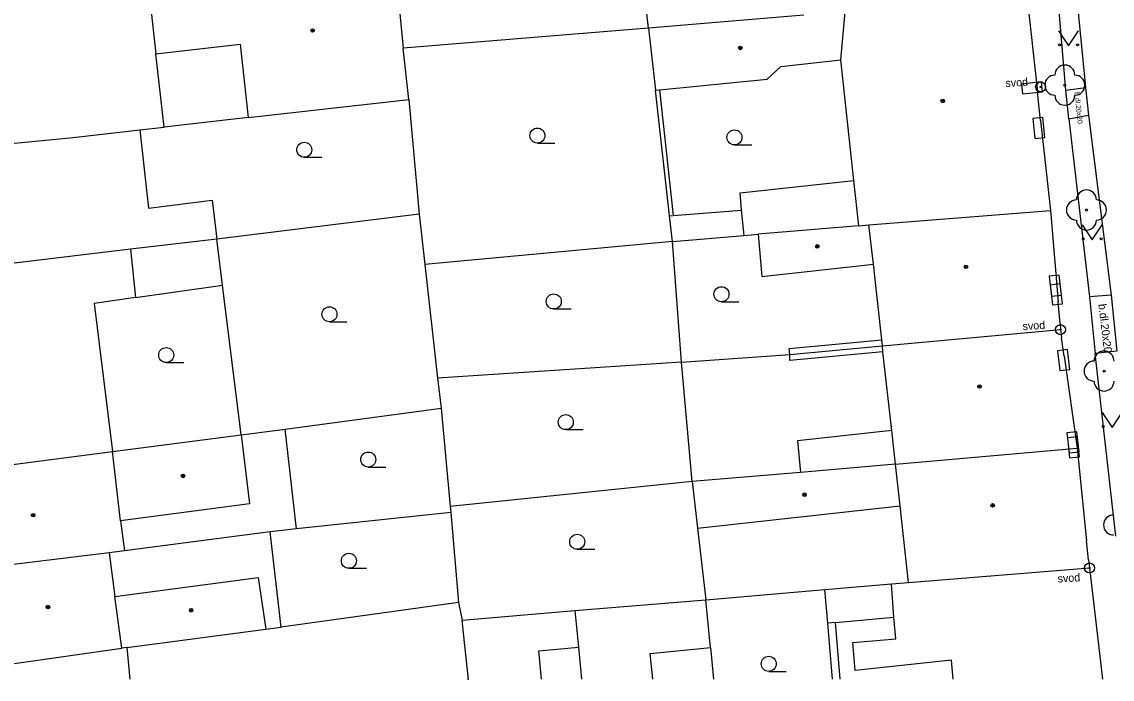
# Model space of a CAD drawing. Extents: x -596229 to -595156, y -1161237 to -1159376.
# Drawn here: x -595832.9 to -595778.4, y -1161235.4 to -1161202.6 of the extents above; entities that cross this region are included whole.
import ezdxf

# ---------------------------------------------------------------- set-up
doc = ezdxf.new("R2010")
doc.units = 0
for name, color, linetype in [('DOP - kresba z DSPS bez souradnic', 7, 'Continuous'), ('DOP - rozhrani ploch obecne', 7, 'Continuous'), ('Level 22', 7, 'Continuous'), ('Level 24', 7, 'Continuous'), ('Level 25', 7, 'Continuous'), ('Level 36', 7, 'Continuous'), ('Level 39', 7, 'Continuous'), ('TM - budovy zdene_ betonove - VP', 7, 'Continuous'), ('TM - chodniky - VP', 7, 'Continuous'), ('TM - komunikace - VP', 7, 'Continuous'), ('TM - plot zdeny_ ohradni zed - VP', 7, 'Continuous'), ('TM - popis povrchu', 7, 'Continuous'), ('TM - poznamka', 7, 'Continuous'), ('TM - rozhrani mezi zpev. plochami mezi sebou - VP', 7, 'Continuous'), ('TM - vstup do budovy - zdene_ betonove', 7, 'Continuous')]:
    doc.layers.add(name, color=color, linetype=linetype)

msp = doc.modelspace()

# ---------------------------------------------------------------- linework, layer by layer
at = {"layer": 'DOP - kresba z DSPS bez souradnic'}
for points in [[(-595801.04, -1161205.96), (-595800.36, -1161212.24)], [(-595797.01, -1161211.11), (-595791.33, -1161210.49)], [(-595796.95, -1161211.98), (-595797.01, -1161211.11)], [(-595800.36, -1161212.24), (-595796.95, -1161211.98)], [(-595796.81, -1161213.24), (-595796.95, -1161211.98)], [(-595800.54, -1161212.26), (-595800.36, -1161212.24)], [(-595827.24, -1161216.34), (-595822.88, -1161215.73)], [(-595794.56, -1161218.89), (-595789.94, -1161218.46)], [(-595794.54, -1161219.19), (-595794.56, -1161218.89)], [(-595789.88, -1161219.05), (-595794.53, -1161219.49)], [(-595794.53, -1161219.49), (-595794.54, -1161219.19)], [(-595789.44, -1161222.99), (-595794.15, -1161223.51)], [(-595794.15, -1161223.51), (-595794, -1161225.08)], [(-595792.25, -1161232.58), (-595792.64, -1161232.62)], [(-595792.25, -1161232.58), (-595789.33, -1161232.32)], [(-595792.018, -1161235.417), (-595792.25, -1161232.58)]]:
    msp.add_lwpolyline(points, dxfattribs=at)
at = {"layer": 'DOP - rozhrani ploch obecne'}
for points in [[(-595801.59, -1161202.89), (-595801.97, -1161199.66)], [(-595801.59, -1161202.89), (-595813.86, -1161203.88)], [(-595800.54, -1161212.26), (-595801.24, -1161205.98)], [(-595813.58, -1161206.44), (-595813.06, -1161212.18)], [(-595813.06, -1161212.18), (-595823.17, -1161213.42)], [(-595813.06, -1161212.18), (-595812.77, -1161214.69)], [(-595800.4, -1161213.54), (-595800.54, -1161212.26)], [(-595822.88, -1161215.73), (-595823.17, -1161213.42)], [(-595800.4, -1161213.54), (-595812.77, -1161214.69)], [(-595800.4, -1161213.54), (-595796.81, -1161213.24)], [(-595799.94, -1161219.57), (-595800.4, -1161213.54)], [(-595796.81, -1161213.24), (-595796.12, -1161213.18)], [(-595812.77, -1161214.69), (-595812.14, -1161220.37)], [(-595821.95, -1161223.2), (-595822.88, -1161215.73)], [(-595794.54, -1161219.19), (-595789.91, -1161218.75)], [(-595799.94, -1161219.57), (-595812.14, -1161220.37)], [(-595799.94, -1161219.57), (-595794.54, -1161219.19)], [(-595799.42, -1161225.54), (-595799.94, -1161219.57)], [(-595812.14, -1161220.37), (-595811.95, -1161221.88)], [(-595819.75, -1161222.92), (-595811.95, -1161221.88)], [(-595811.95, -1161221.88), (-595811.5, -1161226.78)], [(-595821.95, -1161223.2), (-595819.75, -1161222.92)], [(-595819.19, -1161227.9), (-595819.75, -1161222.92)], [(-595799.42, -1161225.54), (-595811.5, -1161226.78)], [(-595811.47, -1161227.08), (-595819.19, -1161227.9)], [(-595811.5, -1161226.78), (-595811.47, -1161227.08)], [(-595811.47, -1161227.08), (-595811.09, -1161231.59)], [(-595820.5, -1161228.05), (-595827.78, -1161229.01)], [(-595819.19, -1161227.9), (-595820.5, -1161228.05)], [(-595819.96, -1161232.81), (-595820.5, -1161228.05)], [(-595799.15, -1161227.87), (-595798.73, -1161231.45)], [(-595798.73, -1161231.45), (-595792.78, -1161230.94)], [(-595792.78, -1161230.94), (-595789.45, -1161230.66)], [(-595792.64, -1161232.62), (-595792.78, -1161230.94)], [(-595811.09, -1161231.59), (-595819.96, -1161232.81)], [(-595811.09, -1161231.59), (-595810.91, -1161232.46)], [(-595805.28, -1161231.99), (-595798.73, -1161231.45)], [(-595798.5, -1161233.84), (-595798.73, -1161231.45)], [(-595810.91, -1161232.46), (-595805.28, -1161231.99)], [(-595805.28, -1161231.99), (-595805.1, -1161233.81)], [(-595810.76, -1161233.9), (-595810.91, -1161232.46)], [(-595792.398, -1161235.417), (-595792.64, -1161232.62)], [(-595820.72, -1161232.91), (-595819.96, -1161232.81)], [(-595810.6, -1161235.41), (-595810.76, -1161233.9)], [(-595810.639, -1161235.417), (-595810.6, -1161235.41)], [(-595810.6, -1161235.41), (-595810.599, -1161235.417)]]:
    msp.add_lwpolyline(points, dxfattribs=at)
at = {"layer": 'Level 22'}
for centre in [(-595780.79, -1161205.73), (-595779.71, -1161211.97), (-595778.83, -1161220.02)]:
    msp.add_circle(centre, 0.05, dxfattribs=at)
for centre, start, end in [((-595780.79, -1161205.23), 0, 180), ((-595781.29, -1161205.73), 90, 270), ((-595780.29, -1161205.73), 270, 90), ((-595780.79, -1161206.23), 180, 0), ((-595779.71, -1161211.47), 0, 180), ((-595780.21, -1161211.97), 90, 270), ((-595779.21, -1161211.97), 270, 90), ((-595779.71, -1161212.47), 180, 0), ((-595778.83, -1161219.52), 0, 180), ((-595779.33, -1161220.02), 90, 270), ((-595778.83, -1161220.52), 180, 0), ((-595778.36, -1161227.71), 90, 270)]:
    msp.add_arc(centre, 0.5, start, end, dxfattribs=at)
at = {"layer": 'Level 24'}
for points in [[(-595781.96, -1161205.568), (-595782.954, -1161205.675), (-595782.9, -1161206.172), (-595781.906, -1161206.065)], [(-595782.392, -1161207.4), (-595782.285, -1161208.394), (-595781.788, -1161208.34), (-595781.895, -1161207.346)], [(-595781.576, -1161215.282), (-595781.46, -1161216.276), (-595780.964, -1161216.218), (-595781.08, -1161215.224)], [(-595781.526, -1161215.722), (-595781.41, -1161216.716), (-595780.914, -1161216.658), (-595781.03, -1161215.664)], [(-595781.154, -1161219.001), (-595781.043, -1161219.995), (-595780.546, -1161219.939), (-595780.657, -1161218.945)], [(-595780.684, -1161223.111), (-595780.573, -1161224.105), (-595780.076, -1161224.049), (-595780.187, -1161223.055)], [(-595780.664, -1161223.361), (-595780.553, -1161224.355), (-595780.056, -1161224.299), (-595780.167, -1161223.305)]]:
    msp.add_lwpolyline(points, close=True, dxfattribs=at)
at = {"layer": 'Level 25'}
for centre, radius in [((-595782, -1161205.82), 0.25), ((-595782, -1161205.82), 0.0303), ((-595781.01, -1161217.95), 0.25), ((-595781.01, -1161217.95), 0.0303), ((-595779.56, -1161229.86), 0.25), ((-595779.56, -1161229.86), 0.0303)]:
    msp.add_circle(centre, radius, dxfattribs=at)
at = {"layer": 'Level 36'}
for p, q in [((-595807.15, -1161208.625), (-595806.275, -1161208.625)), ((-595797.3, -1161208.715), (-595796.425, -1161208.715)), ((-595818.8, -1161209.335), (-595817.925, -1161209.335)), ((-595797.95, -1161216.555), (-595797.075, -1161216.555)), ((-595806.33, -1161216.915), (-595805.455, -1161216.915)), ((-595817.54, -1161217.555), (-595816.665, -1161217.555)), ((-595825.7, -1161219.595), (-595824.825, -1161219.595)), ((-595805.73, -1161222.945), (-595804.855, -1161222.945)), ((-595815.6, -1161224.815), (-595814.725, -1161224.815)), ((-595805.16, -1161228.925), (-595804.285, -1161228.925)), ((-595816.57, -1161229.875), (-595815.695, -1161229.875)), ((-595795.59, -1161235.025), (-595794.715, -1161235.025))]:
    msp.add_line(p, q, dxfattribs=at)
for points in [[(-595781.1, -1161203.01), (-595780.6, -1161203.76), (-595780.1, -1161203.01)], [(-595779.93, -1161212.71), (-595779.43, -1161213.46), (-595778.93, -1161212.71)], [(-595778.93, -1161222.09), (-595778.43, -1161222.84), (-595777.93, -1161222.09)]]:
    msp.add_lwpolyline(points, dxfattribs=at)
for centre, radius in [((-595781.05, -1161203.71), 0.05), ((-595780.151, -1161203.71), 0.05), ((-595807.15, -1161208.25), 0.375), ((-595797.3, -1161208.34), 0.375), ((-595818.8, -1161208.96), 0.375), ((-595779.88, -1161213.41), 0.05), ((-595778.981, -1161213.41), 0.05), ((-595806.33, -1161216.54), 0.375), ((-595797.95, -1161216.18), 0.375), ((-595817.54, -1161217.18), 0.375), ((-595825.7, -1161219.22), 0.375), ((-595805.73, -1161222.57), 0.375), ((-595778.88, -1161222.79), 0.05), ((-595815.6, -1161224.44), 0.375), ((-595805.16, -1161228.55), 0.375), ((-595816.57, -1161229.5), 0.375), ((-595795.59, -1161234.65), 0.375)]:
    msp.add_circle(centre, radius, dxfattribs=at)
at = {"layer": 'Level 39'}
for centre, radius in [((-595818.38, -1161203), 0.09), ((-595818.38, -1161203), 0.0398), ((-595797.01, -1161203.87), 0.09), ((-595797.01, -1161203.87), 0.0398), ((-595786.89, -1161206.52), 0.09), ((-595786.89, -1161206.52), 0.0398), ((-595793.16, -1161213.79), 0.09), ((-595793.16, -1161213.79), 0.0398), ((-595785.73, -1161214.81), 0.09), ((-595785.73, -1161214.81), 0.0398), ((-595785.06, -1161220.79), 0.09), ((-595785.06, -1161220.79), 0.0398), ((-595824.86, -1161225.26), 0.09), ((-595824.86, -1161225.26), 0.0398), ((-595793.8, -1161226.2), 0.09), ((-595793.8, -1161226.2), 0.0398), ((-595784.4, -1161226.73), 0.09), ((-595784.4, -1161226.73), 0.0398), ((-595832.35, -1161227.22), 0.09), ((-595832.35, -1161227.22), 0.0398), ((-595831.61, -1161231.81), 0.09), ((-595831.61, -1161231.81), 0.0398), ((-595824.45, -1161231.97), 0.09), ((-595824.45, -1161231.97), 0.0398)]:
    msp.add_circle(centre, radius, dxfattribs=at)
at = {"layer": 'TM - budovy zdene_ betonove - VP'}
for points in [[(-595814.33, -1161199.05), (-595813.86, -1161203.88)], [(-595826.61, -1161200.53), (-595826.21, -1161204.17)], [(-595782.67, -1161201.38), (-595782.15, -1161206.07)], [(-595791.98, -1161204.47), (-595791.77, -1161202.07)], [(-595793.84, -1161202.24), (-595801.59, -1161202.89)], [(-595801.59, -1161202.89), (-595801.24, -1161205.98)], [(-595826.21, -1161204.17), (-595822.01, -1161203.69)], [(-595822.01, -1161203.69), (-595821.6, -1161207.35)], [(-595825.8, -1161207.83), (-595826.21, -1161204.17)], [(-595813.58, -1161206.44), (-595813.86, -1161203.88)], [(-595795.66, -1161205.43), (-595794.98, -1161204.8)], [(-595794.98, -1161204.8), (-595791.98, -1161204.47)], [(-595791.33, -1161210.49), (-595791.98, -1161204.47)], [(-595801.04, -1161205.96), (-595795.66, -1161205.43)], [(-595801.24, -1161205.98), (-595801.04, -1161205.96)], [(-595821.6, -1161207.35), (-595813.58, -1161206.44)], [(-595782, -1161207.49), (-595781.5, -1161211.99)], [(-595830.35, -1161208.34), (-595827.01, -1161207.97)], [(-595827.01, -1161207.97), (-595825.8, -1161207.83)], [(-595827.01, -1161207.97), (-595826.58, -1161211.87)], [(-595839.85, -1161209.26), (-595830.35, -1161208.34)], [(-595791.08, -1161212.76), (-595791.33, -1161210.49)], [(-595826.58, -1161211.87), (-595823.41, -1161211.48)], [(-595823.41, -1161211.48), (-595823.17, -1161213.42)], [(-595790.58, -1161212.71), (-595781.5, -1161211.99)], [(-595781.5, -1161211.99), (-595781.12, -1161216.56)], [(-595791.08, -1161212.76), (-595796.12, -1161213.18)], [(-595791.08, -1161212.76), (-595790.58, -1161212.71)], [(-595790.36, -1161214.68), (-595790.58, -1161212.71)], [(-595823.17, -1161213.42), (-595827.48, -1161213.93)], [(-595796.12, -1161213.18), (-595795.93, -1161215.3)], [(-595827.48, -1161213.93), (-595839.23, -1161215.35)], [(-595827.48, -1161213.93), (-595827.24, -1161216.34)], [(-595795.93, -1161215.3), (-595790.36, -1161214.68)], [(-595789.94, -1161218.46), (-595790.36, -1161214.68)], [(-595827.24, -1161216.34), (-595829.3, -1161216.64)], [(-595829.3, -1161216.64), (-595828.39, -1161224.04)], [(-595789.91, -1161218.75), (-595781.01, -1161217.95)], [(-595781.03, -1161217.65), (-595781.01, -1161217.95)], [(-595781.01, -1161217.95), (-595780.95, -1161218.34)], [(-595789.91, -1161218.75), (-595789.94, -1161218.46)], [(-595789.88, -1161219.05), (-595789.91, -1161218.75)], [(-595789.44, -1161222.99), (-595789.88, -1161219.05)], [(-595780.82, -1161219.28), (-595780.17, -1161223.88)], [(-595828.39, -1161224.04), (-595821.95, -1161223.2)], [(-595821.95, -1161223.2), (-595821.53, -1161226.66)], [(-595789.25, -1161224.67), (-595789.44, -1161222.99)], [(-595789.25, -1161224.67), (-595780.17, -1161223.88)], [(-595780.17, -1161223.88), (-595779.7, -1161228.51)], [(-595838.13, -1161225.3), (-595828.39, -1161224.04)], [(-595827.98, -1161227.51), (-595828.39, -1161224.04)], [(-595789.25, -1161224.67), (-595794, -1161225.08)], [(-595789.02, -1161226.75), (-595789.25, -1161224.67)], [(-595794, -1161225.08), (-595799.42, -1161225.54)], [(-595799.42, -1161225.54), (-595799.15, -1161227.87)], [(-595821.53, -1161226.66), (-595827.98, -1161227.51)], [(-595799.15, -1161227.87), (-595789.02, -1161226.75)], [(-595788.6, -1161230.59), (-595789.02, -1161226.75)], [(-595827.98, -1161227.51), (-595827.78, -1161229.01)], [(-595828.55, -1161229.11), (-595837.57, -1161230.21)], [(-595827.78, -1161229.01), (-595828.55, -1161229.11)], [(-595828.55, -1161229.11), (-595828.26, -1161231.28)], [(-595788.6, -1161230.59), (-595779.56, -1161229.86)], [(-595779.6, -1161229.45), (-595779.56, -1161229.86)], [(-595779.56, -1161229.86), (-595778.912, -1161235.417)], [(-595828.26, -1161231.28), (-595821.1, -1161230.33)], [(-595821.1, -1161230.33), (-595820.72, -1161232.91)], [(-595789.45, -1161230.66), (-595788.6, -1161230.59)], [(-595789.33, -1161232.32), (-595789.45, -1161230.66)], [(-595827.91, -1161233.87), (-595828.26, -1161231.28)], [(-595789.24, -1161233.4), (-595789.33, -1161232.32)], [(-595827.67, -1161233.83), (-595820.72, -1161232.91)], [(-595791.38, -1161233.58), (-595789.24, -1161233.4)], [(-595791.27, -1161234.99), (-595791.38, -1161233.58)], [(-595837.04, -1161235.17), (-595827.91, -1161233.87)], [(-595827.67, -1161233.83), (-595827.91, -1161233.87)], [(-595827.67, -1161233.83), (-595827.517, -1161235.417)], [(-595807.08, -1161234), (-595805.1, -1161233.81)], [(-595806.942, -1161235.417), (-595807.08, -1161234)], [(-595805.1, -1161233.81), (-595804.946, -1161235.417)], [(-595801.51, -1161234.13), (-595798.5, -1161233.84)], [(-595801.386, -1161235.417), (-595801.51, -1161234.13)], [(-595798.5, -1161233.84), (-595798.344, -1161235.417)], [(-595786.46, -1161234.47), (-595791.27, -1161234.99)], [(-595786.363, -1161235.417), (-595786.46, -1161234.47)]]:
    msp.add_lwpolyline(points, dxfattribs=at)
at = {"layer": 'TM - chodniky - VP'}
for points in [[(-595780.74, -1161205.98), (-595781.15, -1161201.04)], [(-595780.74, -1161205.98), (-595779.75, -1161205.84)], [(-595780.59, -1161207.41), (-595779.61, -1161207.23)], [(-595780.59, -1161207.41), (-595779.55, -1161216.31)], [(-595778.48, -1161216.23), (-595779.55, -1161216.31)], [(-595778.19, -1161219.02), (-595779.28, -1161219.14)], [(-595778.25, -1161228.27), (-595779.28, -1161219.14)]]:
    msp.add_lwpolyline(points, dxfattribs=at)
at = {"layer": 'TM - komunikace - VP'}
for points in [[(-595780.24, -1161200.88), (-595779.75, -1161205.84)], [(-595779.75, -1161205.84), (-595779.61, -1161207.23)], [(-595779.61, -1161207.23), (-595778.48, -1161216.23)], [(-595778.48, -1161216.23), (-595778.19, -1161219.02)]]:
    msp.add_lwpolyline(points, dxfattribs=at)
at = {"layer": 'TM - plot zdeny_ ohradni zed - VP'}
msp.add_lwpolyline([(-595821.6, -1161207.35), (-595825.8, -1161207.83)], dxfattribs=at)
at = {"layer": 'TM - rozhrani mezi zpev. plochami mezi sebou - VP'}
for points in [[(-595780.59, -1161207.41), (-595780.74, -1161205.98)], [(-595779.55, -1161216.31), (-595779.28, -1161219.14)]]:
    msp.add_lwpolyline(points, dxfattribs=at)
at = {"layer": 'TM - vstup do budovy - zdene_ betonove'}
for points in [[(-595782, -1161207.49), (-595782.15, -1161206.07)], [(-595781.03, -1161217.65), (-595781.12, -1161216.56)], [(-595780.82, -1161219.28), (-595780.95, -1161218.34)], [(-595779.6, -1161229.45), (-595779.7, -1161228.51)]]:
    msp.add_lwpolyline(points, dxfattribs=at)

# ---------------------------------------------------------------- texts
at = {"layer": 'TM - popis povrchu'}
for height, rotation, p in [(0.25, 276, (-595780.31, -1161206.09)), (0.4, 276.8485, (-595779.12, -1161216.68))]:
    msp.add_text('b.dl.20x20', height=height, rotation=rotation, dxfattribs=at).set_placement(p)
at = {"layer": 'TM - poznamka'}
for p in [(-595783.75, -1161205.83), (-595782.89, -1161217.98), (-595781.14, -1161230.59)]:
    msp.add_text('svod', height=0.4, rotation=3.4515, dxfattribs=at).set_placement(p)

doc.saveas('drawing.dxf')
